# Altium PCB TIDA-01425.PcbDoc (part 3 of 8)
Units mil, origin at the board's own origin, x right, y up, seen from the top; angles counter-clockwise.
Board outline 7000 x 3600 mil, 6 copper layers (Layer 1 - Top Layer, Layer 2 - GND, Layer 3 - Signal / PWR, Layer 4 - Signal / PWR, Layer 5 - PWR, Layer 6 - Bottom Layer), stack 60.4 mil thick; 495 components, 307 nets, 2058 pads, 1870 vias.
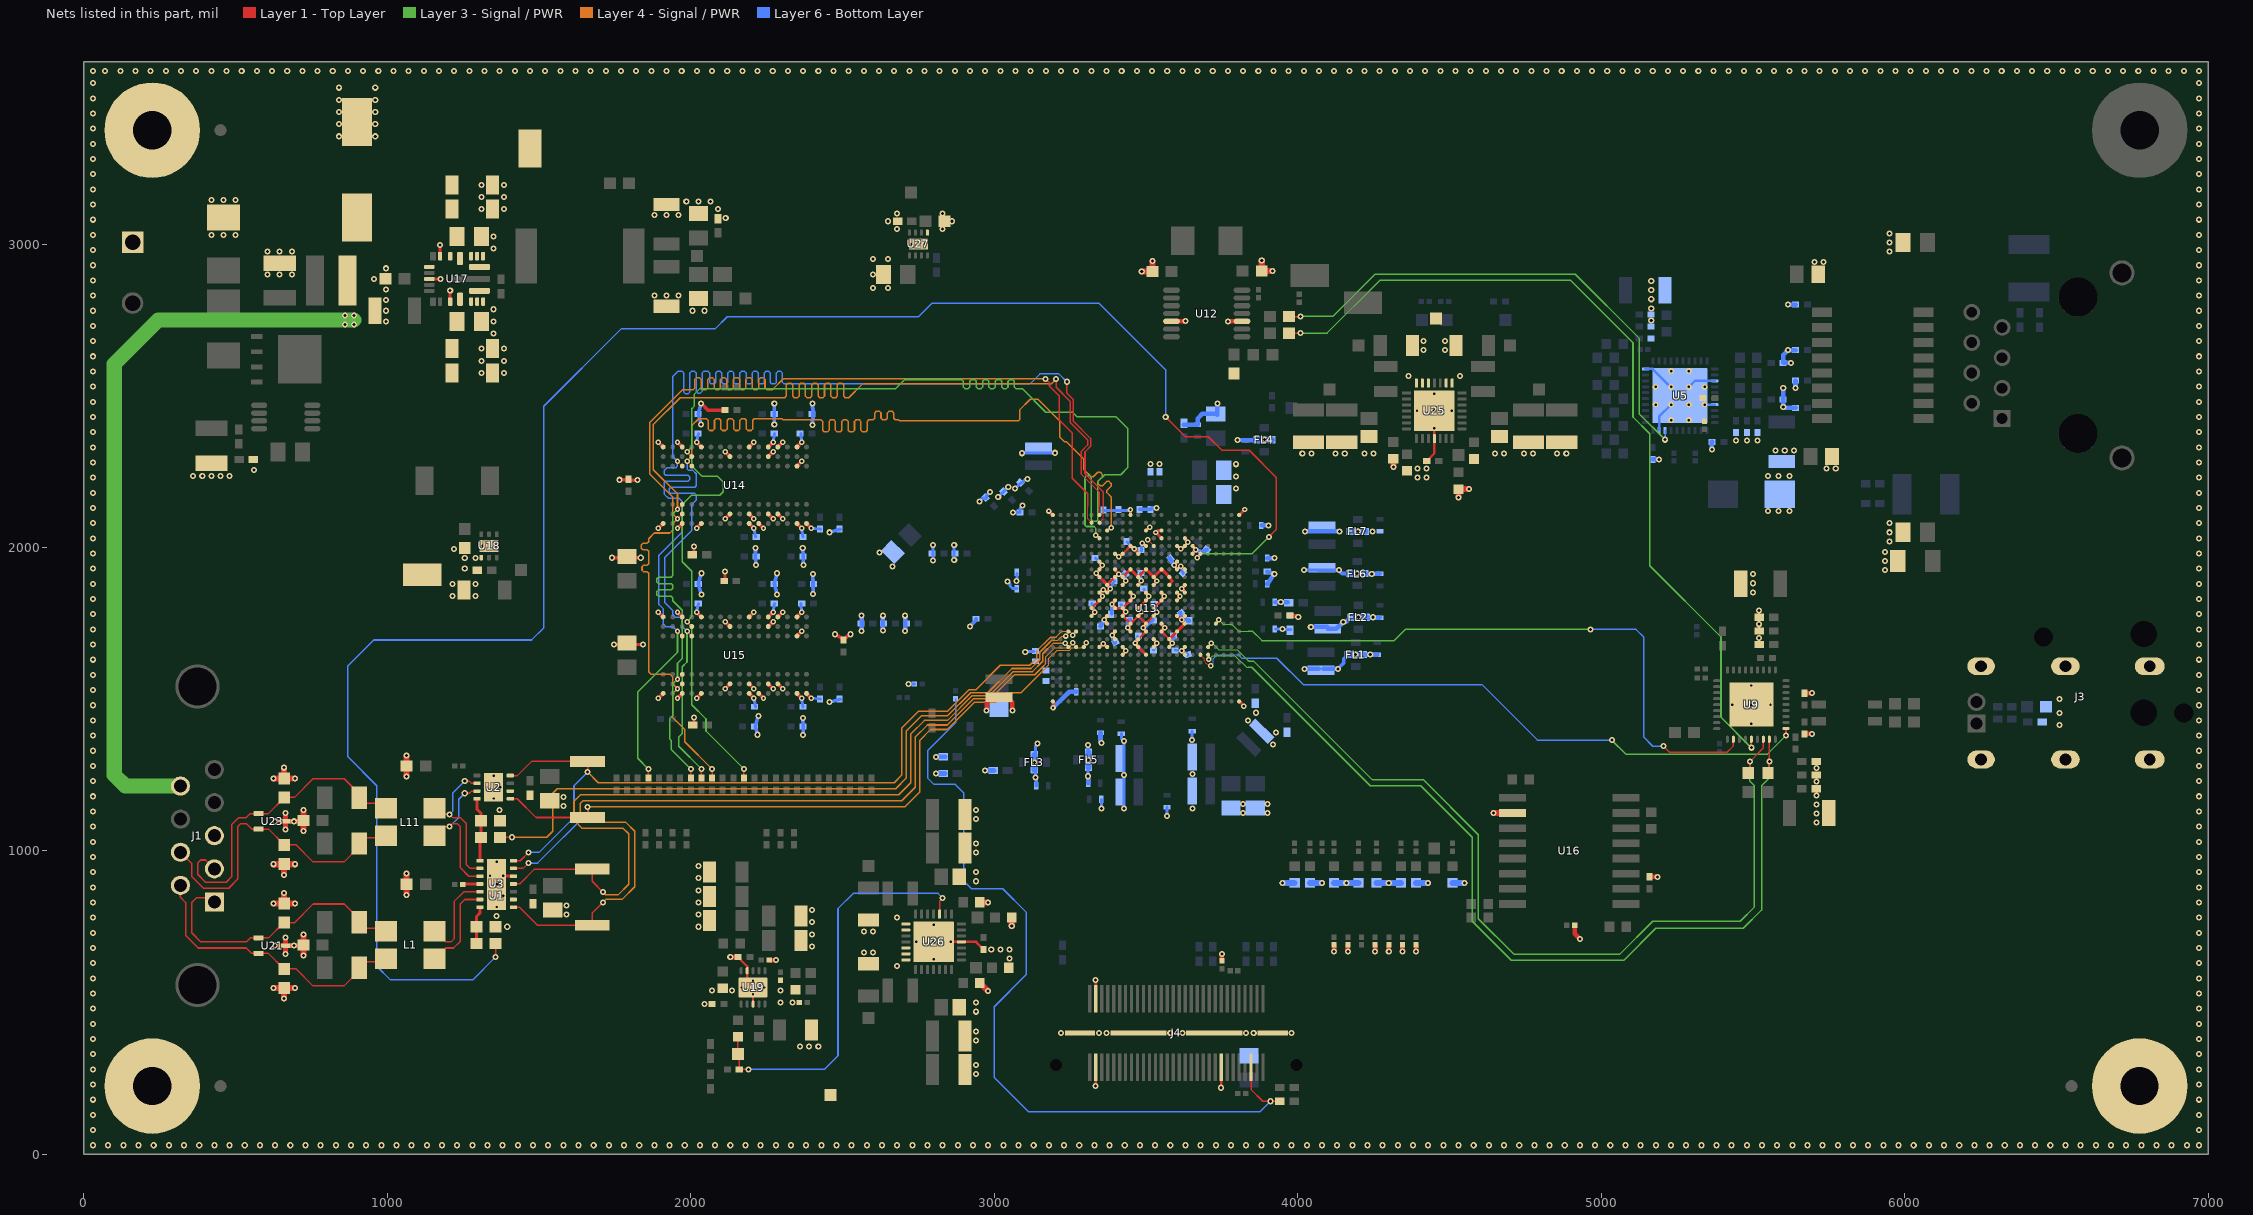
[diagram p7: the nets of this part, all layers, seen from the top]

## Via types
v1: diameter 20, hole 10, Layer 1 - Top Layer to Layer 6 - Bottom Layer, tented both sides, 1119 vias
v2: diameter 20, hole 9.99, Layer 1 - Top Layer to Layer 6 - Bottom Layer, tented both sides, 298 vias
v3: diameter 18, hole 7.99, Layer 1 - Top Layer to Layer 6 - Bottom Layer, tented both sides, 203 vias
v4: diameter 18, hole 8, Layer 1 - Top Layer to Layer 6 - Bottom Layer, tented both sides, 177 vias
v5: diameter 19.68, hole 7.87, Layer 1 - Top Layer to Layer 6 - Bottom Layer, tented both sides, 41 vias
v6: diameter 20, hole 10, Layer 1 - Top Layer to Layer 6 - Bottom Layer, 27 vias
v7: diameter 19.68, hole 7.87, Layer 1 - Top Layer to Layer 6 - Bottom Layer, 5 vias

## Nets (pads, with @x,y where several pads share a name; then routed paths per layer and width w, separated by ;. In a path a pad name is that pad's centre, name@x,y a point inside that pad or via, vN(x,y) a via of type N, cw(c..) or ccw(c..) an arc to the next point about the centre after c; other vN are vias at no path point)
BOARD_12V: C164.1 C169.1 C170.1 C171.1 C172.1 C175.1 C176.1 J1.9 L4.2 U17.4 U17.14 U17.15 U17.18 | length 2438.3
  Layer 3 - Signal / PWR w50: J1.9@318.11,1213.58 136.42,1213.58 100,1250 100,2605 245,2750 890,2750
  other v1: 860,2735 890,2735 860,2765 890,2765
CAN1_STB: R4.1 R6.2 U1.8 U3.14 | length 123.9
  Layer 1 - Top Layer w10: R4.1@1293.5,695 R6.2@1293.5,750 1293.5,783.5 1304.88,794.88 U3.14@1304.88,814.23
CAN2_STB: R8.1 R10.2 U2.8 U3.8 | length 211
  Layer 1 - Top Layer w10: U2.8@1294.88,1171.61 1294.88,1138.12 1308.51,1124.49 R10.2@1308.51,1098.9 1308.51,1038.9 1304.88,1035.28 U3.8@1304.88,967.77
CAN_VIO: R3.1 U1.5 U3.11 | length 55.9
  Layer 1 - Top Layer w10: R3.1@1248.98,890.98 U3.11@1304.88,891
CANH_1: L1.2 U1.7 U3.13 | length 303.2
  Layer 1 - Top Layer w5: L1.2@1154.72,644.72 1157.72,644.72 1193,680 1218.28,680 1240,701.72 1240,825 1254.8,839.8 U3.13@1304.88,839.82
CANH_1_OUT: C248.1 J1.6 L1.1 R7.1 U21.2 | length 944
  Layer 1 - Top Layer w5: J1.6@318.11,886.42 318.11,846.89 335,830 335,721.72 376.72,680 535,680 552.99,662.01 U21.2@575.71,662.01 607.99,662.01 658.5,611.5 C248.1@660,611.5 698.5,611.5 755,555 857,555 907.09,605.09 R7.1@907.09,615 927.09,635 985.55,635 L1.1@995.28,644.72
CANH_2: L11.2 U2.7 U3.10 | length 489.3
  Layer 1 - Top Layer w5: L11.2@1154.72,1054.72 1180,1080 v1(1205,1080) 1215,1090 1230,1090 1240,1080 1240,945 1268.41,916.59 U3.10@1304.88,916.59 ; v1(1255,1190) 1270,1190 1277.2,1197.2 U2.7@1294.88,1197.2
  Layer 6 - Bottom Layer w5: v1(1205,1080) 1235,1110 1235,1170 v1(1255,1190)
CANH_2_OUT: C163.1 J1.7 L11.1 R151.1 U23.2 | length 1037
  Layer 1 - Top Layer w5: J1.7@318.11,995.47 355,958.58 355,916 394,877 477,877 507,907 507,1080 517,1090 535,1090 552.99,1072.01 U23.2@575.71,1072.01 607.99,1072.01 C163.1@660,1020 ; C163.1@660,1019.09 C163.1@660,1020 ; L11.1@995.28,1053.23 985.55,1043.5 927.09,1043.5 907.09,1023.5 907.09,1013.59 857,963.5 755,963.5 698.5,1020 C163.1@660,1020
CANL_1: L1.3 U1.6 U3.12 | length 305.5
  Layer 1 - Top Layer w5: L1.3@1154.72,735.28 1157.72,735.28 1193,700 1210,700 1220,710 1220,833.28 1252.11,865.39 U3.12@1304.88,865.41
CANL_1_OUT: C1.1 J1.1 L1.4 R5.2 U21.1 | length 934.6
  Layer 1 - Top Layer w5: J1.1@429.92,831.89 416.81,845 370,845 355,830 355,730 385,700 535,700 548.19,713.19 U21.1@575.71,713.19 608.19,713.19 658.5,763.5 C1.1@660,763.5 693.5,763.5 755,825 858,825 907.09,775.91 R5.2@907.09,765 927.09,745 985.55,745 L1.4@995.28,735.28
CANL_2: L11.3 U2.6 U3.9 | length 486.9
  Layer 1 - Top Layer w5: L11.3@1154.72,1145.28 1180,1120 v1(1205,1120) 1215,1110 1240,1110 1260,1090 1260,955 1272.82,942.18 U3.9@1304.88,942.18 ; v1(1255,1230) 1270,1230 1277.2,1222.8 U2.6@1294.88,1222.8
  Layer 6 - Bottom Layer w5: v1(1205,1120) 1215,1130 1215,1190 v1(1255,1230)
CANL_2_OUT: C160.1 J1.2 L11.4 R150.2 U23.1 | length 1040.5
  Layer 1 - Top Layer w5: J1.2@440.87,930 J1.2@429.92,940.94 400.87,970 385,970 375,960 375,923 401,897 468.72,897 487,915.28 487,1087 510,1110 535,1110 548.19,1123.19 U23.1@575.71,1123.19 608.19,1123.19 660,1175 C160.1@660,1176.1 693.5,1176.1 755,1237.6 858,1237.6 907.09,1188.51 907.09,1177.6 927.09,1157.6 985.55,1157.6 L11.4@995.28,1147.87
DCAN1_RX: "CAN1 RX.1" U1.4 U3.4 U13.H23 | length 2859.9
  Layer 1 - Top Layer w4: v3(3233.7,1684.9) U13.H23@3244.09,1672.05
  Layer 1 - Top Layer w5: U3.4@1415.12,891 1436,891 1485,940 1675,940 1675,900 v2(1710,865)
  Layer 4 - Signal / PWR w5.25: v2(1710,865) 1720,855 1760,855 1795,890 1795,1056.72 1776.72,1075 1641.72,1075 1615,1101.72 1615,1163.28 1636.72,1185 2685,1185 2725,1225 2725,1385 2770,1430 2845.51,1430 2926.49,1510.99 2926.99,1510.99 2982.51,1511 3062.39,1590.88 3125.87,1590.88 3160,1625.01 3160,1625.5 3160.01,1650 3194.91,1684.9 v3(3233.7,1684.9)
DCAN1_STB: R4.2 U13.Y6 | length 6312.5
  Layer 1 - Top Layer w5: v1(1356.5,650) R4.2@1356.5,695 ; v1(3565,2430) 3630,2365 3705,2365 3750,2320 3840,2320 3930,2230 3930,2060 v1(3905,2035)
  Layer 1 - Top Layer w10: v3(3669.2,1966.7) U13.Y6@3679.13,1979.13
  Layer 3 - Signal / PWR w5.25: v3(3669.2,1966.7) 3681.64,1979.13 3849.13,1979.13 v1(3905,2035)
  Layer 6 - Bottom Layer w5: v1(1356.5,650) 1281.5,575 1010,575 965,620 965,1215 870,1310 870,1610 955,1695 1475,1695 1515,1735 1515,2465 1770,2720 2080,2720 2120,2760 2750,2760 2795,2805 3345,2805 3565,2585 v1(3565,2430)
DCAN1_TX: "CAN1 TX.1" U1.1 U3.1 U13.H22 | length 2900.1
  Layer 1 - Top Layer w4: v3(3258.1,1686) 3267.4,1674.34 U13.H22@3269.68,1672.05
  Layer 1 - Top Layer w5: U3.1@1415.12,814.23 1435.77,814.23 1495,755 1675,755 1675,795 v2(1710,830)
  Layer 4 - Signal / PWR w4: 3163,1610.51 3170,1617.51 3170,1620.51 3170.25,1620.76 3170.25,1621.25 3170.27,1640.26 3200.01,1670 3227.4,1670 3227.49,1669.91 3239.91,1669.91 3240,1670 3245,1670 3258.1,1683.1 v3(3258.1,1686)
  Layer 4 - Signal / PWR w5.25: v2(1710,830) 1720,840 1773.28,840 1815,881.72 1815,1065 1785,1095 1650,1095 1635,1110 1635,1155 1645,1165 2695,1165 2740,1210 2740,1375 2780,1415 2845.01,1415 2930.74,1500.74 2931.24,1500.74 2986.76,1500.75 3066.64,1580.63 3133.12,1580.63 3163,1610.51
DCAN2_RX: "CAN2 RX.1" U2.4 U3.7 U13.K22 | length 2683.3
  Layer 1 - Top Layer w4: v3(3259.3,1710.7) U13.K22@3269.68,1723.23
  Layer 1 - Top Layer w5: U2.4@1405.12,1248.39 1428.39,1248.39 1475,1295 1660,1295 ; U3.7@1415.12,967.77 1437.77,967.77 v1(1465,995)
  Layer 1 - Top Layer w5.25: v1(1660,1260) 1660,1295
  Layer 4 - Signal / PWR w4: 3204.56,1705.15 3222.55,1723.14 3246.86,1723.14 v3(3259.3,1710.7)
  Layer 4 - Signal / PWR w5.25: v1(1660,1260) 1695,1225 2670,1225 2695,1250 2695,1405 2750,1460 2845.5,1460 2916.99,1531.5 2939.98,1531.5 3019.86,1611.38 3116.88,1611.38 3139.5,1634 3139.5,1649.99 3139.49,1658.48 3184.91,1703.9 3203.31,1703.9 3204.56,1705.15
  Layer 6 - Bottom Layer w5: v1(1465,995) 1500,995 1615,1110 1615,1215 v1(1660,1260)
DCAN2_STB: R8.2 U13.K23 | length 2336.2
  Layer 1 - Top Layer w4: v3(3236.1,1708.1) 3244.09,1715.59 U13.K23@3244.09,1723.23
  Layer 1 - Top Layer w5: R8.2@1371.5,1045 v1(1410,1045)
  Layer 4 - Signal / PWR w4: 3186.17,1690.66 3190.17,1694.66 3209.66,1694.66 3223.1,1708.1 v3(3236.1,1708.1)
  Layer 4 - Signal / PWR w5.25: v1(1410,1045) 1525,1045 1545,1065 1545,1190 1560,1205 2675,1205 2710,1240 2710,1395 2760,1445 2846.01,1445 2922.24,1521.24 2922.74,1521.24 2978.26,1521.25 3058.14,1601.13 3121.13,1601.13 3149.76,1629.76 3149.76,1647.75 3149.75,1654.24 3186.17,1690.66
DCAN2_TX: "CAN2 TX.1" U2.1 U3.6 U13.H21 | length 2651.5
  Layer 1 - Top Layer w4: U13.H21@3295.28,1672.05 v3(3303.2,1685.7)
  Layer 1 - Top Layer w5: U3.6@1415.12,942.18 1447.18,942.18 v1(1465,960)
  Layer 1 - Top Layer w5.25: U2.1@1405.12,1171.61 1428.39,1171.61 1490,1110 1660,1110 v1(1660,1145)
  Layer 4 - Signal / PWR w4: 3163,1596.01 3180,1613.01 3180,1635 3207.01,1662.01 3224.09,1662.01 3224.18,1661.92 3243.22,1661.92 3243.31,1662.01 3248.31,1662.01 3255.65,1669.35 3286.85,1669.35 v3(3303.2,1685.7)
  Layer 4 - Signal / PWR w5.25: v1(1660,1145) 2705,1145 2755,1195 2755,1365 2790.13,1400.13 2845.13,1400.13 2905.37,1460.37 ; 2905.37,1460.4 2915.11,1470.14 ; 2915.14,1470.14 2935.5,1490.5 3005.58,1490.5 3035.71,1520.63 3087.62,1520.63 3163,1596.01
  Layer 6 - Bottom Layer w5: v1(1465,960) 1495,960 1660,1125 v1(1660,1145)
"DDR EN": R69.2 R145.1 TP63.1 U26.10 | length 1368
  Layer 1 - Top Layer w5: R69.2@2155,387.44 TP63.1@2155,330 2159.68,325.32 R145.1@2159.68,280 v1(2190,280) ; U26.10@2819.69,791.54 2819.69,834.69 v1(2830,845)
  Layer 6 - Bottom Layer w5: v1(2190,280) 2440,280 2485,325 2485,810 2535,860 2815,860 v1(2830,845)
EMU_RSTN: J4.6 R52.1 R114.1 | length 2722.9
  Layer 1 - Top Layer w5: J4.6@3846.07,287.21 3846.07,213.93 3885,175 v1(3910,175) R52.1@3941.38,175
  Layer 6 - Bottom Layer w5: R114.1@2873,1502.01 2873,1423 2780,1330 2780,1240 2800,1220 2870,1220 2900,1190 2900,900 2925,875 3028.28,875 3105,798.28 3105,591.57 3000,486.57 3000,253.43 3113.43,140 3875,140 v1(3910,175)
ENET_EN: R34.2 U9.7 U13.H5 | length 3075.3
  Layer 1 - Top Layer w4: U13.H5@3704.8,1672 3713.11,1683.64 3714.13,1683.81 v3(3714.7,1684.6)
  Layer 1 - Top Layer w5: R34.2@5485,1256.5 5490,1261.5 v2(5490,1295) 5534.37,1339.37 U9.7@5534.37,1367.83
  Layer 3 - Signal / PWR w4: v3(3714.7,1684.6) 3715.3,1684 3718,1684 3739.68,1662.32 3801.48,1662.32 3836.8,1627 3837,1627
  Layer 3 - Signal / PWR w5.25: 3837,1627 3838.37,1625.63 3854.37,1625.63 4245,1235 4413.43,1235 4595,1053.43 4595,776.72 4711.72,660 5061.72,660 5170.25,768.54 5458.54,768.54 5505,815 5505,1215 5490,1230 v2(5490,1295)
ENET_INH: U9.10 U13.G6 | length 2158.6
  Layer 1 - Top Layer w4: U13.G6@3679.13,1646.46 3691.69,1633.9 3691.69,1626.62 3695.02,1619.77 3701.2,1615.1 3711.36,1612.89 v3(3713.4,1609.7)
  Layer 1 - Top Layer w5.25: v1(5609.17,1380) U9.10@5609.17,1403.26
  Layer 3 - Signal / PWR w5.25: v1(5035,1365) 5081,1319 5548.17,1319 v1(5609.17,1380)
  Layer 6 - Bottom Layer w4: v3(3713.4,1609.7) 3721.84,1618.14 3721.84,1633.84 3734.1,1646.1 3804.9,1646.1 3816,1635
  Layer 6 - Bottom Layer w5: 3816,1635 3931,1635 4018,1548 4607,1548 4790,1365 v1(5035,1365)
ENET_INTSN: U9.2 U13.L4 | length 2147.2
  Layer 1 - Top Layer w4: U13.L4@3730.4,1748.8 v3(3740.3,1761.6)
  Layer 1 - Top Layer w5: v1(5205,1345) 5225,1325 5415,1325 5435.94,1345.94 U9.2@5435.94,1367.83
  Layer 3 - Signal / PWR w4: v3(3740.3,1761.6) 3755.39,1746.51 3783,1746.51 3806.26,1723.25 3837,1723.25
  Layer 3 - Signal / PWR w5.25: 3837,1723.25 3851.75,1723.25 3882,1693 4318,1693 4355,1730 v2(4965,1730)
  Layer 6 - Bottom Layer w5: v2(4965,1730) 5115,1730 5140,1705 5140,1375 5170,1345 v1(5205,1345)
ENET_WAKE: R35.2 U9.8 U13.G5 | length 3102.5
  Layer 1 - Top Layer w4: U13.G5@3704.72,1646.46 v3(3706.85,1630.85)
  Layer 1 - Top Layer w5: R35.2@5550,1256.5 5554.06,1260.55 v2(5554.06,1295) U9.8@5554.06,1367.83
  Layer 3 - Signal / PWR w4: v3(3706.85,1630.85) 3719.8,1643.8 3792.83,1643.8 3831.5,1605.13 3837,1605.13
  Layer 3 - Signal / PWR w5.25: 3837,1605.13 3848.87,1605.13 4239,1215 4405.15,1215 4575,1045.15 4575,768.43 4703.43,640 5075,640 5180,745 5468.28,745 5528.54,805.25 5528.54,1215 5554.06,1240.52 v2(5554.06,1295)
ETH_CLK0: R1.2 U5.28 | length 1699.5
  Layer 1 - Top Layer w5: R1.2@3971.5,2760.92 4008.81,2760.92 v1(4009.41,2761.52)
  Layer 3 - Signal / PWR w5.25: v1(4009.41,2761.52) 4116.52,2761.52 4255,2900 4915,2900 5125,2690 5125,2440.79 v1(5210.79,2355)
  Layer 6 - Bottom Layer w5: v1(5210.79,2355) U5.28@5210.79,2385.83
ETH_CLK1: R19.2 U9.5 | length 2814.9
  Layer 1 - Top Layer w5: R19.2@3971.5,2705.92 4008.81,2705.92 v1(4009.41,2706.52) ; v1(5495,1340) U9.5@5495,1367.83
  Layer 3 - Signal / PWR w5.25: v1(4009.41,2706.52) 4096.52,2706.52 4270,2880 4900,2880 5105,2675 5105,2430 5160,2375 5160,1940 5395,1705 5395,1440 v1(5495,1340)
GND: "GND 3V3Buck.1" "GND 5V0Boost.1" C1.2 C2.2 C3.2 C4.2 C5.2 C6.2 C7.2 C8.1 C9.2 C10.2 C11.1 C12.1 C13.2 C14.1 C15.2 C16.2 C17.2 C18.2 C19.2 C21.2 C22.2 C23.2 C24.2 C25.2 C27.2 C28.2 C29.2 C30.2 C31.2 C32.2 C33.2 C34.2 C35.2 C36.2 C37.2 C38.2 C39.2 C40.2 C41.2 C42.2 C43.2 C44.2 C45.2 C46.2 C47.2 C48.2 C49.2 C50.2 C51.2 C52.2 C53.2 C54.2 C55.2 C56.2 C57.2 C58.2 C59.2 C60.2 C62.2 C63.2 C64.2 C65.2 C66.2 C67.2 C68.2 C69.2 C70.2 C71.2 C72.2 C73.2 C74.2 C75.2 C76.2 C77.2 C79.2 C80.2 C81.2 C82.2 C83.2 C84.2 C85.2 C86.2 C87.2 C88.2 C89.2 C90.2 C91.2 C92.2 C93.2 C94.2 C95.2 C96.2 C97.2 C98.2 C99.2 C100.2 C101.2 C102.2 C103.2 C104.2 C105.2 C106.2 C107.2 C108.2 C109.2 C110.2 C111.2 C112.2 C113.2 C114.2 C115.2 C116.2 C117.2 C118.2 C119.2 C120.2 C122.2 C123.2 C124.2 C125.2 C126.2 C127.2 C128.2 C129.2 C130.2 C131.1 C132.1 C133.2 C134.2 C135.2 C136.2 C137.2 C138.2 C139.2 C140.2 C141.2 C142.2 C147.2 C149.2 C150.2 C151.2 C152.2 C153.2 C154.2 C155.2 C156.2 C157.2 C158.2 C159.2 C160.2 C161.2 C163.2 C164.2 C166.2 C167.1 C168.2 C169.2 C170.2 C171.2 C172.2 C173.2 C174.2 C175.2 C176.2 C177.2 C178.2 C179.2 C180.2 C183.2 C184.2 C185.2 C186.2 C187.2 C188.2 C189.2 C190.2 C191.2 C192.2 C193.2 C194.2 C195.2 C196.2 C197.2 C198.2 C199.2 C222.2 C228.2 C229.2 C230.2 C231.2 C232.2 C233.2 C234.2 C235.2 C236.2 C237.2 C238.2 C239.2 C240.2 C241.2 C242.2 C243.2 C244.2 C245.2 C246.2 C247.2 C248.2 C249.2 C250.2 C251.2 C252.2 C253.2 C255.2 C256.2 C257.2 C258.2 C259.2 C260.2 C261.2 C262.2 C263.2 C264.2 C265.2 C266.2 C267.2 C268.2 C269.2 C270.2 C271.2 D3.1 FL1.2 FL2.2 FL3.2 FL4.2 FL5.2 FL6.2 FL7.2 H1.1 H3.1 H4.1 J1.3 J3.S1 J3.S2 J3.S3 J3.S4 J3.S5 J3.S6 J4.16 J4.57 J4.58 J4.MP1 J4.MP2 J4.MP3 J4.MP4 J5.1 R6.1 R10.1 R21.2 R28.1 R36.1 R37.1 R43.2 R45.2 R47.2 R58.1 R59.1 R79.2 R95.2 R98.1 R103.1 R105.2 R106.2 R107.1 R110.2 R111.1 R117.1 R119.2 R121.1 R123.2 R125.1 R127.1 TP1.1 TP2.1 U1.2 U1.9@1360,852.6 U2.2 U2.9@1350,1210 U3.2 U3.5 U3.15 U4.2 U5.13 U5.17 U5.29 U5.40 U5.41@5260,2500 U6.2 U7.2 U8.2 U9.37 U10.2 U11.2 U12.5 U12.10 U13.A1 U13.A25 U13.AA7 U13.AA8 U13.AA9 U13.AA12 U13.AA13 U13.AA15 U13.AB8 U13.AB11 U13.AC11 U13.AC13 U13.AE1 U13.AE15 U13.AE25 U13.G8 U13.G13 U13.G16 U13.H8 U13.H10 U13.H12 U13.H14 U13.H16 U13.H18 U13.H19 U13.J10 U13.J12 U13.J14 U13.J17 U13.K9 U13.K11 U13.K13 U13.K15 U13.K17 U13.L8 U13.L11 U13.L13 U13.L15 U13.L18 U13.M8 U13.M9 U13.M12 U13.M14 U13.M16 U13.M18 U13.M20 U13.N12 U13.N14 U13.N16 U13.N17 U13.N20 U13.P9 U13.P11 U13.P13 U13.P15 U13.P17 U13.P19 U13.R8 U13.R9 U13.R11 U13.R13 U13.R15 U13.R18 U13.R19 U13.T8 U13.T10 U13.T12 U13.T14 U13.T16 U13.T18 U13.U10 U13.U12 U13.U14 U13.U16 U13.U17 U13.U19 U13.V8 U13.V9 U13.V11 U13.V13 U13.V15 U13.V17 U13.V19 U13.W9 U13.W19 U13.Y7 U13.Y14 U13.Y16 U13.Y17 U14.A9 U14.B1 U14.B3 U14.B9 U14.D1 U14.D8 U14.E1 U14.E2 U14.E8 U14.F9 U14.G1 U14.G8 U14.G9 U14.J2 U14.J8 U14.M1 U14.M9 U14.P1 U14.P9 U14.T1 U14.T9 U15.A9 U15.B1 U15.B3 U15.B9 U15.D1 U15.D8 U15.E1 U15.E2 U15.E8 U15.F9 U15.G1 U15.G8 U15.G9 U15.J2 U15.J8 U15.M1 U15.M9 U15.P1 U15.P9 U15.T1 U15.T9 U16.10 U17.3 U17.5 U17.6 U17.7 U17.8 U17.10 U17.11 U17.12 U17.13 U17.16 U17.20 U18.1 U18.7@1335,2005 U19.4 U19.8 U19.11 U21.3 U23.3 U25.4 U25.15 U25.16 U25.19 U25.20 U25.21 U25.29 U26.4 U26.15 U26.16 U26.19 U26.20 U26.21 U26.29 U27.5 U27.9 | length 12469.8
  Layer 1 - Top Layer w4: v3(3506.4,2024.8) 3525.59,2005.61 U13.AA12@3525.59,2004.72
  Layer 1 - Top Layer w8: C187.2@2155.32,650 2155.32,649.68 2185.32,619.68 U19.4@2185.32,605.12 U19.11@2185.32,569.68 ; U19.8@2205,494.88 v5(2205,527.36) ; v7(2857.09,700) U26.4@2891.54,700 2940,700 C266.2@2964.69,675.31 ; U13.N20@3320.87,1800 U13.P19@3346.46,1825.59 ; v1(3334.26,225.01) J4.58@3334.26,287.21 ; J4.57@3334.26,512.8 v1(3334.26,575) ; U13.N17@3397.64,1800 U13.N16@3423.23,1800 U13.P15@3448.82,1825.59 ; U13.M16@3423.23,1774.41 U13.L15@3448.82,1748.82 U13.M14@3474.41,1774.41 U13.L13@3500,1748.82 U13.M12@3525.59,1774.41 ; U13.Y16@3423.23,1979.13 U13.AA15@3448.82,2004.72 ; U13.J14@3474.41,1697.64 U13.K13@3500,1723.23 ; U13.N14@3474.41,1800 U13.P13@3500,1825.59 ; U13.N12@3525.59,1800 U13.P11@3551.18,1825.59 ; U13.K11@3551.18,1723.23 U13.J10@3576.77,1697.64 ; v1(3747.64,219.42) J4.16@3747.64,287.21 ; C247.2@4425.31,2285 4425.31,2285.31 4450,2310 U25.4@4450,2358.46 v5(4450,2392.91)
  Layer 1 - Top Layer w10: U17.20@1138.19,2885 v1(1175,2885) ; U17.16@1173.62,2959.8 v1(1173.62,2996.61) ; U17.3@1207.09,2810.2 v1(1207.09,2847.01) ; U3.15@1385.59,916.59 U3.5@1415.12,916.59 ; v1(1740,1966) v1(1835,1966) ; v1(1747.5,1680.5) v1(1842.5,1680.5) ; R37.1@2010,1410 v1(2010,1440) ; R36.1@2010,1970 v1(2010,2002.5) ; C79.2@2112.5,1890 v1@2112.5,1920.5 ; U15.G8@2192.24,1550.51 v4(2207.98,1534.77) ; U13.A25@3192.91,1492.91 3192.91,1477.09 3193.59,1476.41 v3(3193.59,1471.22) ; U13.M20@3320.83,1774.43 v3(3330.5,1787.1) U13.N20@3320.87,1800 ; U13.W19@3346.4,1953.6 U13.W19@3346.46,1953.54 3356,1944 v3(3356,1941) 3356,1937.6 3346.4,1928 v3(3336.4,1914.9) U13.U19@3346.46,1902.36 U13.T18@3372.05,1876.77 ; U13.H19@3346.46,1672.05 v3(3359.03,1682.37) 3358.89,1682.59 3359.09,1682.43 U13.H18@3372.05,1672.05 ; U13.P19@3346.46,1825.59 v3(3356.7,1838.8) U13.R19@3346.43,1851.16 ; U13.R19@3346.43,1851.22 v3(3359.2,1860.4) 3372.05,1851.18 v3(3381.5,1863.9) U13.T18@3372.05,1876.77 ; U13.Y17@3397.6,1979.2 3397.66,1979.16 v3(3410.3,1969.6) U13.Y16@3423.23,1979.13 ; U13.V17@3397.64,1927.95 v3(3410.7,1912.2) ; U13.T16@3423.23,1876.77 v3(3432.8,1889.6) U13.U16@3423.23,1902.36 ; U13.G16@3423.23,1646.46 v3(3433.1,1659.1) U13.H16@3423.23,1672.05 ; U13.AE15@3448.82,2107.09 v3(3448.82,2124.04) ; U13.H14@3474.41,1672.05 U13.G13@3500,1646.46 ; U13.T14@3474.41,1876.77 v3(3484.25,1889.65) U13.U14@3474.41,1902.36 ; U13.AC13@3500,2056 3511.8,2066 v3(3512.3,2066) ; U13.H12@3525.59,1672.05 v3(3534.8,1684.8) U13.J12@3525.59,1697.64 ; U13.M12@3525.59,1774.41 v3(3535.4,1787) U13.N12@3525.59,1800 ; U13.T12@3525.59,1876.77 v3(3535.5,1889.4) U13.U12@3525.59,1902.36 ; U13.AB11@3551.2,2030.4 3551,2030.4 v3(3532.1,2049.3) 3538.8,2056 U13.AC11@3551.2,2056 ; U13.H10@3576.77,1672.05 v3(3586.85,1684.65) U13.J10@3576.77,1697.64 U13.L8@3627.95,1748.82 v3(3617.7,1761.7) ; U13.U10@3576.77,1902.36 U13.V11@3551.18,1927.95 ; U13.T10@3576.77,1876.77 3587.1,1889.4 3580.2,1896.3 3580.2,1900.3 3552.55,1927.95 U13.V11@3551.18,1927.95 ; U13.M9@3602.36,1774.41 v3(3617.7,1761.7) ; U13.W9@3602.4,1953.6 U13.W9@3602.36,1953.54 v3(3592.5,1940.9) 3602.36,1927.95 v3(3615,1937.7) U13.V8@3627.95,1927.95 ; U13.G8@3627.95,1646.46 v3(3617.5,1659.3) U13.H8@3627.95,1672.05 ; U13.M8@3627.95,1774.41 v3(3617.7,1761.7) ; U13.A1@3807.09,1492.91 v3(3822.7,1477.3) ; U13.AE1@3807.09,2107.09 v3(3825,2125) ; U13.T18@3372.05,1876.77 U13.U17@3397.64,1902.36 v3(3410.7,1912.2) ; v3(3410.7,1912.2) U13.U16@3423.23,1902.36 ; U13.U16@3423.23,1902.36 3448.82,1927.95 U13.U14@3474.41,1902.36 ; U13.U14@3474.41,1902.36 3500,1927.95 U13.U12@3525.59,1902.36 ; U13.U12@3525.59,1902.36 U13.V11@3551.18,1927.95
  Layer 1 - Top Layer w12: v1(1765,2223) C72.2@1794.96,2222.5 ; C72.2@1795,2222.5 v1(1824,2222) ; v4(1893.03,1503.26) U15.T9@1908.78,1519.02 ; v4(1893.03,1786.73) U15.T1@1908.78,1770.98 ; v4(1893.03,2063.26) U14.T9@1908.78,2079.02 ; v4(1893.03,2346.73) U14.T1@1908.78,2330.98 ; v4(1956.03,1503.27) U15.P9@1971.77,1519.02 ; v4(1956.03,1786.72) U15.P1@1971.77,1770.98 ; v4(1956.03,2063.27) U14.P9@1971.77,2079.02 ; v4(1956.03,2346.72) U14.P1@1971.77,2330.98 ; v4(2019.02,1503.27) U15.M9@2034.76,1519.02 ; v4(2019.02,1786.72) U15.M1@2034.76,1770.98 ; v4(2019.02,2063.27) U14.M9@2034.76,2079.02 ; v4(2019.02,2346.72) U14.M1@2034.76,2330.98 ; v1(2033.94,2475) 2056.44,2452.5 C62.2@2111.44,2452.5 ; v4(2113.51,1534.77) U15.J8@2129.25,1550.51 ; v4(2113.51,1755.22) U15.J2@2129.25,1739.49 ; v4(2113.51,2094.77) U14.J8@2129.25,2110.51 ; v4(2113.51,2315.22) U14.J2@2129.25,2299.49 ; U15.G9@2192.24,1519.02 v4(2207.98,1503.27) ; U15.G1@2192.24,1770.98 v4(2207.98,1786.72) ; U14.G9@2192.24,2079.02 v4(2207.98,2063.27) ; U14.G8@2192.24,2110.51 v4(2207.98,2094.77) ; U14.G1@2192.24,2330.98 v4(2207.98,2346.72) ; U15.F9@2223.74,1519.02 v4(2239.49,1503.26) ; U14.F9@2223.74,2079.02 v4(2239.49,2063.26) ; U15.E8@2255.24,1550.51 v4(2270.98,1534.77) ; U15.E2@2255.24,1739.49 v4(2270.98,1755.22) ; U15.E1@2255.24,1770.98 v4(2270.98,1786.72) ; U14.E8@2255.24,2110.51 v4(2270.98,2094.77) ; U14.E2@2255.24,2299.49 v4(2270.98,2315.22) ; U14.E1@2255.24,2330.98 v4(2270.98,2346.72) ; U15.D8@2286.73,1550.51 v4(2302.47,1534.77) ; U15.D1@2286.73,1770.98 v4(2302.47,1786.72) ; U14.D8@2286.73,2110.51 v4(2302.47,2094.77) ; U14.D1@2286.73,2330.98 v4(2302.47,2346.72) ; U15.B9@2349.72,1519.02 v4(2365.46,1503.27) ; U15.B3@2349.72,1707.99 v4(2365.46,1723.73) ; U15.B1@2349.72,1770.98 v4(2365.46,1786.72) ; U14.B9@2349.72,2079.02 v4(2365.46,2063.27) ; U14.B3@2349.72,2267.99 v4(2365.46,2283.73) ; U14.B1@2349.72,2330.98 v4(2365.46,2346.72) ; U15.A9@2381.22,1519.02 v4(2396.97,1503.26) ; U14.A9@2381.22,2079.02 v4(2396.97,2063.26) ; v1(2475,1714) 2502.5,1697.5 v1(2526,1714) ; v3(3180,2120) U13.AE25@3192.91,2107.09 ; U13.L18@3372.05,1748.82 v3(3362.5,1761.5) U13.M18@3372.05,1774.41 ; U13.J17@3397.64,1697.64 v3(3388.4,1710.5) U13.K17@3397.64,1723.23 ; U13.N17@3397.64,1800 v3(3388,1813) U13.P17@3397.64,1825.59 ; U13.M16@3423.23,1774.41 v3(3433,1787.5) U13.N16@3423.23,1800 ; U13.K15@3448.82,1723.23 v3(3439.5,1736) U13.L15@3448.82,1748.82 ; U13.P15@3448.82,1825.59 v3(3458.1,1838.5) U13.R15@3448.82,1851.18 ; U13.AA15@3448.82,2004.72 v3(3461.5,1995) U13.Y14@3474.4,1979.2 ; U13.H14@3474.41,1672.05 v3(3465,1685) U13.J14@3474.41,1697.64 ; U13.M14@3474.41,1774.41 v3(3484,1787.5) U13.N14@3474.41,1800 ; v3(3487.1,2013.8) U13.AA13@3500,2004.72 ; U13.K13@3500,1723.23 v3(3490.5,1736) U13.L13@3500,1748.82 ; U13.P13@3500,1825.59 v3(3509.5,1838.5) U13.R13@3500,1851.18 ; U13.K11@3551.18,1723.23 v3(3561.5,1736) U13.L11@3551.18,1748.82 ; U13.P11@3551.18,1825.59 v3(3560.5,1838.5) U13.R11@3551.18,1851.18 ; U13.P9@3602.36,1825.59 v3(3612,1838.5) U13.R9@3602.36,1851.18 ; U13.AA9@3602.36,2004.72 v3(3615.2,1995.2) 3627.94,2004.75 U13.AA8@3628,2004.8 ; U13.R8@3627.95,1851.18 v3(3618,1864) U13.T8@3627.95,1876.77 ; U13.AB8@3628.02,2030.37 v3(3637.5,2017.5) ; U13.Y7@3653.54,1979.13 v3(3663.5,1992) U13.AA7@3653.54,2004.72 ; C156.2@3974.69,1775 3997.65,1775 v1(4001.74,1770.91)
  Layer 1 - Top Layer w15: v1(630,687.6) U21.3@664.29,687.6 ; v1(630,1097.6) U23.3@664.29,1097.6 ; v1(664.29,660) U21.3@664.29,687.6 ; v1(664.29,715.2) U21.3@664.29,687.6 ; v1(664.29,1070) U23.3@664.29,1097.6 ; v1(664.29,1125.2) U23.3@664.29,1097.6 ; C2.2@721.1,687.6 v1(692.7,687.6) U21.3@664.29,687.6 ; C161.2@721.1,1097.6 v1(692.7,1097.6) U23.3@664.29,1097.6 ; v1(2130,650) C187.2@2155.32,650 ; C196.2@2257.99,640 v1(2280,640) ; v2(2975,1463) 2975,1490.5 2990.98,1506.47 C110.2@3016,1506.47 3043.4,1506.47 3059.6,1490.27 v2(3059.6,1463) ; U12.5@3583.86,2745.33 v1@3629.41,2745.33 ; R59.1@3750,637.99 v1(3750,660) ; v1@3770.59,2745.33 U12.10@3816.14,2745.33 ; v1(4120.08,668) R121.1@4120.08,690.01 ; v1(4165.08,668) R103.1@4165.08,690.01 ; v1(4255.08,668) R125.1@4255.08,690.01 ; v1(4300.08,668) R111.1@4300.08,690.01 ; v1(4345.08,668) R107.1@4345.08,690.01 ; v1(4390.08,668) R117.1@4390.08,690.01 ; R127.1@4912.99,755 4912.99,727.01 v1(4930,710) ; C7.2@5160,914.68 v1(5185.31,914.68) ; U11.2@5670,1385.32 v1(5695,1385.32) ; U10.2@5670,1519.68 v1(5695,1519.68)
  Layer 1 - Top Layer w20: v1(625,548.5) C248.2@660,548.5 ; v1(625,826.5) C1.2@660,826.5 ; v1(625,956.1) C163.2@660,956.1 ; v1(625,1239.09) C160.2@660,1239.09 ; v1(660,513.5) C248.2@660,548.5 ; v1(660,861.5) C1.2@660,826.5 ; v1(660,921.1) C163.2@660,956.1 ; v1(660,1274.09) C160.2@660,1239.09 ; v1(695,548.5) C248.2@660,548.5 ; v1(695,826.5) C1.2@660,826.5 ; v1(695,956.1) C163.2@660,956.1 ; v1(695,1239.09) C160.2@660,1239.09 ; v1(723.5,655) C2.2@723.5,690 v1(723.5,725) ; v1(723.5,1065) C161.2@723.5,1100 v1(723.5,1135) ; v1(1063.5,855) C252.2@1063.5,890 v1(1063.5,925) ; v1(1063.5,1245) C253.2@1063.5,1280 v1(1063.5,1315) ; C264.2@2952.56,565 v2(2978.78,538.78) ; C265.2@2952.56,830 v2(2980,830) ; v2(3057.56,752.56) C268.2@3057.56,780 ; v1(3486,2909.42) C222.2@3521,2909.42 v1(3521,2944.42) ; v1(3881.5,2945.92) C194.2@3881.5,2910.92 v1(3916.5,2910.92) ; v2(4315,2265) C245.2@4315,2292.44 ; v2(4530,2165) C250.2@4530,2192.44 v2(4565,2192.44) ; C246.2@4580,2292.44 C246.2@4582.56,2292.44 ; v1(4645,1125) U16.10@4707.99,1125
  Layer 6 - Bottom Layer w8: U5.40@5145.83,2588.58 5169.42,2588.58 5228.87,2529.13 v5(5230.87,2529.13) ; U5.29@5191.1,2385.83 5191.1,2431.1 v5(5230.87,2470.87) ; v5(5289.13,2529.13) 5309.21,2549.21 U5.13@5374.17,2549.21 ; v5(5340.71,2470.87) 5341.1,2470.47 U5.17@5374.17,2470.47
  Layer 6 - Bottom Layer w10: v4(2019.02,1786.72) 2024.99,1814.94 C83.2@2025,1815 ; v4(2019.02,2346.72) 2024.96,2374.78 C67.2@2025,2375 ; v4(2207.98,1503.27) 2212.43,1475.44 C80.2@2212.5,1475 ; v4(2207.98,2063.27) C65.2@2212.5,2035 ; v4(2270.98,1786.72) C82.2@2275,1814.96 ; v4(2270.98,2346.72) C68.2@2275,2374.96 ; C81.2@2362.5,1815 2362.53,1814.71 v4(2365.46,1786.72) ; C69.2@2362.5,2375 v4(2365.46,2346.72) ; v4(2365.46,1503.27) 2369.99,1475.05 C85.2@2370,1475 ; v4(2365.46,2063.27) 2369.99,2035.05 C63.2@2370,2035 ; v4(2396.97,1503.26) C84.2@2425,1500.31 C84.2@2427.5,1500 ; v4(2396.97,2063.26) C66.2@2425,2060.31 C66.2@2427.5,2060 ; v1(2718,1550) C231.2@2737.01,1550 ; v2(2798,1957) v2(2798,2008) ; v2(2868,1958) v2(2868,2008) ; v2(2952,2152) 2962.14,2162.14 2974.86,2162.14 2974.86,2171.86 v2(2986,2183) ; v2(3013,2166) 3029.86,2182.86 3029.86,2183.14 3030.14,2183.14 v2(3046,2199) ; v1(3043.87,1887.84) 3051.8,1879.91 3051.8,1873 3060.2,1864.6 C33.2@3074.6,1864.6 ; v2(3061.68,2115) 3084.68,2115 3084.68,2129 v2(3093.68,2138) ; v2(3069,2194) 3088.14,2213.14 3091.14,2213.14 3103,2225 v2(3110,2225) ; v2(3073.8,1890) 3074.8,1891 C45.2@3074.8,1914 ; v2(3092,2310.5) v2@3200,2310.5 ; v1(3102.04,1655.01) v1@3102.61,1655.01 ; v1@3104,1656.4 v1@3102.61,1655.01 ; C130.2@3130.5,1656.7 3106.89,1656.7 3105.2,1655.01 v1@3102.61,1655.01 ; v2(3136.4,1242.4) 3135.7,1243.1 3135.7,1345 3142,1351.3 v1(3142,1353.5) ; v2(3309.2,1246) v2(3309.2,1348.7) ; C129.2@3321.5,1815 3321.61,1814.65 v3(3330.5,1787.1) ; C138.2@3333,1965 3356,1942 v3(3356,1941) ; v1(3353,1140) C43.2@3353,1170 ; C126.2@3358,2121 3445.78,2121 v3(3448.82,2124.04) ; v3(3381.5,1863.9) 3395.68,1888.43 C139.2@3396,1889 ; C36.2@3387.1,1780.3 3387.1,1812.1 v3(3388,1813) ; v3(3410.7,1912.2) 3430.86,1912.2 3432.51,1913.86 C140.2@3432.92,1913.89 ; C102.2@3417.5,1812.5 3418.51,1810.88 v3(3433,1787.5) ; C38.2@3418.6,1386.2 3418.6,1371.4 v1(3427.9,1362.1) 3428,1362 v2(3428,1250) v2(3428,1140) ; C140.2@3431.92,1912.08 3432.8,1911.2 v3(3432.8,1889.6) ; C51.2@3438,2018 v3(3461.5,1995) ; v3(3465,1685) C115.2@3472,1707.2 ; C95.2@3482,1915 v3(3484.25,1889.65) ; C42.2@3485.5,1989 3485.57,1989.98 3485.69,1991.85 v3(3487.1,2013.8) ; v3(3490.5,1736) 3498,1736 C96.2@3524,1762 ; C97.2@3493,1863.5 v3(3509.5,1838.5) ; C105.2@3525.2,1661.6 v3(3534.8,1684.8) ; C34.2@3527.5,1813 v3(3535.4,1787) ; v1(3569,1115.7) C53.2@3569,1144 ; v3(3586.85,1684.65) C103.2@3592.4,1706.6 ; C106.2@3596,1662.8 3596.14,1662.77 v3(3617.5,1659.3) ; v3(3615,1937.7) 3621.7,1916.03 3621.81,1915.68 3622,1915.05 3622.09,1914.77 C128.2@3622.14,1914.59 ; v2@3651.5,1364.5 v2(3652,1365) C40.2@3652,1395 ; C44.2@3926.5,1731.5 v2(3950.2,1731.5) 3951.5,1730.2 C15.2@3978.2,1730.2 ; v2(4021,1925) C10.2@4068.1,1925
  Layer 6 - Bottom Layer w12: v1(2033.94,2405) C76.2@2023.94,2440 v1(2033.94,2475) ; v1(2035,1845) 2025,1880 v1(2035,1915) ; v1(2213,1998) 2212.5,1970.05 2212.5,1970 2212.53,1969.74 v1(2215,1942) ; v1(2220.27,1382.79) 2212.5,1410 v1(2222.5,1445) ; v1(2275,2405) v1(2275,2475) ; v1(2284.69,1845) C89.2@2274.69,1880 v1(2284.69,1915) ; v1(2368.86,1998.04) 2370,1970.01 v1(2371,1942) ; v1(2369,1438) 2370,1410.01 v1(2370,1382) ; v1(2401,2403) 2402.5,2439.89 2402.5,2440 2402.5,2440.12 v1(2401,2475) ; v1(2401.92,1912.95) C87.2@2402.5,1880 ; C87.2@2402.5,1879.97 v1(2403,1847) ; v1(2457.5,1490) 2490.27,1499.36 C88.2@2492.5,1500 ; v1(2457.5,2050) 2490.27,2059.36 C71.2@2492.5,2060 ; v1(2920,1740) 2940,1760 C149.2@2940,1765 ; v2(3136.4,1242.4) 3138,1240.8 C41.2@3138,1215 ; v3(3448.82,2124.04) v3@3449.78,2125 ; C153.2@3479,2125.31 C155.2@3515,2125.31 3519.69,2130 v1(3535,2130) ; v2(3801.61,2354) C46.2@3827,2354 ; FL4.2@3905,2355 FL4.2@3914.61,2355 ; C157.2@3975,1775 3997.65,1775 v1(4001.74,1770.91) ; C10.2@4068.1,1925 4133.8,1925 4134.5,1925.7 4146.2,1914 FL6.2@4171.39,1914 ; v2(4132.2,1600) 4152.2,1620 4152.2,1632.8 FL1.2@4166.39,1647 ; 4207.7,1914 4208.7,1913 v2(4244,1913)
  Layer 6 - Bottom Layer w15: v2(2563,1724) v2(2563,1776) ; v2(2633,1726) v2(2633,1775) ; v2(2706,1725) v2(2706,1775) ; v1(2808.62,1255) C122.2@2831.38,1255 C122.2@2838.62,1255 ; v1(2808.62,1310) C116.2@2831.38,1310 C116.2@2838.62,1310 ; v2(2970,1265) C32.2@3000,1265 ; v3(3193.59,1471.22) 3247.37,1525 C52.2@3270,1525 ; C50.2@3309,1223 3309,1245.79 v2(3309.2,1246) ; C37.2@3350,1390 3350,1359.4 v1(3353.2,1356.2) ; C152.2@3350,1740 v3(3362.5,1761.5) ; v3(3388.4,1710.5) 3396.68,1687.28 3396.94,1686.53 C47.2@3397.1,1686.08 ; v3(3439.5,1736) 3439.5,1753.5 C94.2@3448,1762 ; C239.2@3576.98,1966.26 3579.02,1962.92 v3(3592.5,1940.9) ; C125.2@3612.74,1785.52 3612.98,1784.36 3613.05,1784.02 v3(3617.7,1761.7) 3639.99,1759.34 3641.97,1759.13 3643.04,1759.02 C114.2@3643.22,1759 ; v3(3617.5,1659.3) C104.2@3635.43,1646.67 ; C49.2@3625,2405 C58.2@3670,2405 3670,2425 3685,2440 3733,2440 3735,2438 3735,2445 v2(3735,2475) ; v3(3663.5,1992) 3684.6,1984.8 C59.2@3699.52,1992.81 ; C46.2@3827,2354 3864.39,2354 FL4.2@3865.39,2355 ; C64.2@3881,2072.8 v1(3904.3,2072.8) ; C39.2@3899.7,1878.91 3900.3,1879.8 v2(3922.7,1913.21) C154.2@3900,1920 ; C54.2@3900,1965 v1(3923,1965) ; C55.2@3926,1819.7 v2(3944.1,1819.7) C48.2@3967,1820 ; v2(4021.8,1600) C27.2@4069,1600 ; v1@4024,2053.1 4087.8,2053.1 v2(4137,2053) v2@4140,2053 ; v1(4043,1738) C9.2@4098,1738 ; C27.2@4085,1600 v2(4132.2,1600) ; C9.2@4099,1731.47 4127.47,1731.47 4150,1754 v1(4150,1755) 4160.39,1755 FL2.2@4175.39,1770 ; FL1.2@4215.61,1646 C31.2@4262,1646 ; FL2.2@4224.61,1769 C35.2@4271,1769 ; v2(4244,1913) C56.2@4271,1913 ; C11.1@5170,2290.32 v1(5190,2290.32) ; v1(5365,2323) 5365,2347.68 C12.1@5365.31,2348 ; C4.2@5599.69,2488 5599.69,2463.31 v1(5600,2463) 5603,2460 U7.2@5640.31,2460 ; C4.2@5600,2488 v1(5600,2525) ; v1(5615.32,2800) U4.2@5640.32,2800 ; v1(5625,2608) C3.2@5599.69,2608 5599.69,2634.37 v1(5615.32,2650) U6.2@5640.32,2650 ; v1(5640.32,2525) U8.2@5640.32,2550
  Layer 6 - Bottom Layer w20: FL3.2@3132,1267.39 FL3.2@3132,1316.61 ; FL5.2@3311,1275.39 FL5.2@3311,1324.61 ; FL4.2@3865.39,2355 FL4.2@3914.61,2355 ; v1(3950,894.45) R123.2@3990,894.45 ; R119.2@4040,894.45 v1(4080,894.45) ; R105.2@4120,894.45 v1(4160,894.45) R110.2@4200,894.45 ; FL1.2@4166.39,1647 FL1.2@4215.61,1647 ; FL6.2@4171.39,1914 4207.7,1914 FL6.2@4220.61,1914 ; FL7.2@4173.39,2053 v1(4198,2053) FL7.2@4222.61,2053 ; FL2.2@4175.39,1770 FL2.2@4224.61,1770 ; R106.2@4260,894.45 v1(4300,894.45) R45.2@4340,894.45 ; R47.2@4390,894.45 v1(4430,894.45) ; R43.2@4510,894.45 v1(4550,894.45)
  other v1: 30,30 80,30 130,30 180,30 230,30 280,30 330,30 380,30 430,30 480,30 530,30 580,30 630,30 680,30 730,30 780,30 830,30 880,30 930,30 980,30 1030,30 1080,30 1130,30 1180,30 1230,30 1280,30 1330,30 1380,30 1430,30 1480,30 1530,30 1580,30 1630,30 1680,30 1730,30 1780,30 1830,30 1880,30 1930,30 1980,30 2030,30 2080,30 2130,30 2180,30 2230,30 2280,30 2330,30 2380,30 2430,30 2480,30 2530,30 2580,30 2630,30 2680,30 2730,30 2780,30 2830,30 2880,30 2930,30 2980,30 3030,30 3080,30 3130,30 3180,30 3230,30 3280,30 3330,30 3380,30 3430,30 3480,30 3530,30 3580,30 3630,30 3680,30 3730,30 3780,30 3830,30 3880,30 3930,30 3980,30 4030,30 4080,30 4130,30 4180,30 4230,30 4280,30 4330,30 4380,30 4430,30 4480,30 4530,30 4580,30 4630,30 4680,30 4730,30 4780,30 4830,30 4880,30 4930,30 4980,30 5030,30 5080,30 5130,30 5180,30 5230,30 5280,30 5330,30 5380,30 5430,30 5480,30 5530,30 5580,30 5630,30 5680,30 5730,30 5780,30 5830,30 5880,30 5930,30 5980,30 6030,30 6080,30 6130,30 6180,30 6230,30 6280,30 6330,30 6380,30 6430,30 6480,30 6530,30 6580,30 6630,30 6680,30 6730,30 6780,30 6830,30 6880,30 6930,30 6970,30 30,80 6970,80 30,130 6970,130 30,180 6970,180 30,230 6970,230 30,280 6970,280 30,330 6970,330 2360,355 2390,355 2420,355 30,380 6970,380 3220,400 3345,400 3370,400 3580,400 3620,400 3830,400 3855,400 3980,400 30,430 6970,430 30,480 6970,480 2045,495 2295,500 2335,500 30,530 6970,530 2070,540 2135,540 2295,540 30,580 6970,580 30,630 6970,630 30,680 6970,680 2400,685 2400,725 30,730 6970,730 1395,750 2025,750 2400,765 30,780 6970,780 1360,785 1590,790 2025,790 2400,805 1590,820 30,830 2025,830 6970,830 2025,870 30,880 6970,880 2025,910 30,930 6970,930 2025,950 30,980 6970,980 30,1030 6970,1030 30,1080 6970,1080 5710,1093 5710,1123 30,1130 6970,1130 1370,1135 1580,1147.4 5710,1153 1580,1177.4 30,1180 6970,1180 5710,1183 5710,1228 30,1230 6970,1230 5710,1273 30,1280 6970,1280 3132,1292 3311,1300 30,1330 6970,1330 30,1380 6970,1380 6510,1415 30,1430 6970,1430 6510,1455 30,1480 6970,1480 6510,1500 30,1530 6970,1530 30,1580 6970,1580 30,1630 6970,1630 4191,1647 4239,1647 30,1680 6970,1680 5520,1702 30,1730 6970,1730 5520,1747 4200,1770 4248,1770 30,1780 6970,1780 5520,1792 30,1830 6970,1830 1215,1840 1290,1840 5500,1852 30,1880 1215,1880 1290,1880 6970,1880 5500,1882 5500,1912 4196,1914 2112,1921 5935,1925 30,1930 1255,1930 6970,1930 5935,1955 1255,1965 1290,1965 30,1980 6970,1980 5935,1985 1220,1995 5950,2020 30,2030 6970,2030 5950,2050 4024,2053 4247,2053 30,2080 5950,2080 6970,2080 5550,2120 5585,2120 5620,2120 30,2130 6970,2130 30,2180 6970,2180 30,2230 6970,2230 360,2235 390,2235 420,2235 450,2235 480,2235 5550,2235 5585,2235 5620,2235 560,2255 5743.07,2260 5773.07,2260 30,2280 6970,2280 5575,2320 5605,2320 5635,2320 30,2330 6970,2330 5445,2353 5480,2353 5515,2353 3890,2355 30,2380 6970,2380 30,2430 6970,2430 30,2480 6970,2480 30,2530 6970,2530 1310,2575 1385,2575 30,2580 6970,2580 1310,2614.37 1385,2615 30,2630 6970,2630 1310,2655 1385,2655 30,2680 6970,2680 1350,2705 30,2730 6970,2730 995,2745 1350,2745 3770,2744.74 3630,2745.92 5165,2748 30,2780 995,2780 2005,2780 2045,2780 6970,2780 1350,2785 5165,2788 995,2815 5165,2818 30,2830 1880,2830 1920,2830 1960,2830 6970,2830 5165,2848 995.28,2850 2600,2855 2650,2855 5165,2878 30,2880 6970,2880 955.28,2885 605,2900 645,2900 685,2900 2600,2900 995.28,2920 30,2930 6970,2930 5702.34,2940 5732.34,2940 2600,2950 2650,2950 605,2975 645,2975 685,2975 5950,2975 30,2980 6970,2980 1350,2985 5950,3005 1350,3025 30,3030 420,3030 460,3030 500,3030 6970,3030 5950,3035 2680,3050 2830,3050 2650,3075 2860,3075 30,3080 6970,3080 2115,3085 1880,3095 1920,3095 1960,3095 2680,3100 2830,3100 1310,3115 1385,3115 2090,3115 30,3130 6970,3130 1985,3140 2025,3140 2065,3140 420,3145 460,3145 500,3145 1310,3155 1385,3155 30,3180 6970,3180 1310,3195 1385,3195 30,3230 6970,3230 30,3280 6970,3280 30,3330 6970,3330 840,3355 960,3355 30,3380 6970,3380 840,3395 960,3395 30,3430 6970,3430 840,3435 960,3435 840,3475 960,3475 30,3480 6970,3480 840,3515 960,3515 30,3530 6970,3530 30,3570 70,3570 120,3570 170,3570 220,3570 270,3570 320,3570 370,3570 420,3570 470,3570 520,3570 570,3570 620,3570 670,3570 720,3570 770,3570 820,3570 870,3570 920,3570 970,3570 1020,3570 1070,3570 1120,3570 1170,3570 1220,3570 1270,3570 1320,3570 1370,3570 1420,3570 1470,3570 1520,3570 1570,3570 1620,3570 1670,3570 1720,3570 1770,3570 1820,3570 1870,3570 1920,3570 1970,3570 2020,3570 2070,3570 2120,3570 2170,3570 2220,3570 2270,3570 2320,3570 2370,3570 2420,3570 2470,3570 2520,3570 2570,3570 2620,3570 2670,3570 2720,3570 2770,3570 2820,3570 2870,3570 2920,3570 2970,3570 3020,3570 3070,3570 3120,3570 3170,3570 3220,3570 3270,3570 3320,3570 3370,3570 3420,3570 3470,3570 3520,3570 3570,3570 3620,3570 3670,3570 3720,3570 3770,3570 3820,3570 3870,3570 3920,3570 3970,3570 4020,3570 4070,3570 4120,3570 4170,3570 4220,3570 4270,3570 4320,3570 4370,3570 4420,3570 4470,3570 4520,3570 4570,3570 4620,3570 4670,3570 4720,3570 4770,3570 4820,3570 4870,3570 4920,3570 4970,3570 5020,3570 5070,3570 5120,3570 5170,3570 5220,3570 5270,3570 5320,3570 5370,3570 5420,3570 5470,3570 5520,3570 5570,3570 5620,3570 5670,3570 5720,3570 5770,3570 5820,3570 5870,3570 5920,3570 5970,3570 6020,3570 6070,3570 6120,3570 6170,3570 6220,3570 6270,3570 6320,3570 6370,3570 6420,3570 6470,3570 6520,3570 6570,3570 6620,3570 6670,3570 6720,3570 6770,3570 6820,3570 6870,3570 6920,3570 6970,3570
  other v2: 2940,265 2940,295 2940,375 2940,405 2940,470 2940,500 2680,620 3050,645 2570,665 2600,665 2990,675 3020,675 3050,675 2570,735 2600,735 2680,780 2940,900 2940,930 2940,995 2940,1025 2940,1105 3820,1125 3900,1125 2940,1135 3653,1140 3820,1155 3900,1155 3653,1253 3918,1350 3929,1390 3836.2,1430.2 3861.9,1455.3 4136,1925 2665,1937 2622,1984 3796,2194.27 4395,2230 4425,2230 3796,2234.27 4395,2260 4425,2260 3796,2274.27 3515,2275 3545,2275 4015,2310 4045,2310 4125,2310 4155,2310 4220,2310 4250,2310 4650,2310 4680,2310 4745,2310 4775,2310 4855,2310 4885,2310 3200,2312 4365,2565 4535,2565 4415,2650 4485,2650 4415,2680 4485,2680
  other v5: 2167.6,550 2242.4,550 2205,572.64 1360,815.2 1338.35,852.6 1381.65,852.6 1360,890 1338.35,918.17 1381.65,918.17 1360,963.83 1350,1172.6 1328.35,1210 1371.65,1210 1350,1247.4 5495,1419.01 5432.01,1482 5495,1482 5557.99,1482 5495,1544.99 1313.35,2005 1356.65,2005 5230.87,2419.29 5289.13,2419.29 4392.91,2450 4450,2450 4507.09,2450 5179.29,2470.87 5289.13,2470.87 4450,2507.09 5179.29,2529.13 5340.71,2529.13 5230.87,2580.71 5289.13,2580.71 2728.35,3000 2771.65,3000
  other v7: 2800,642.91 2742.91,700 2800,700 2800,757.09
H_DDR1_A0: R67.1 U13.AC18 U14.N3 U15.N3 | length 3986.7
  Layer 1 - Top Layer w4: v4(1987.53,1723.73) U15.N3@2003.27,1707.99 ; v4(1987.53,2283.73) U14.N3@2003.27,2267.99 ; U13.AC18@3372.05,2055.91 v3(3384.9,2065.2)
  Layer 1 - Top Layer w5: R67.1@2035,1239.68 v1(2035,1270)
  Layer 3 - Signal / PWR w5.25: v4(1987.53,1723.73) 1987.53,1622.53 1971.7,1606.7 1971.7,1386.7 1960,1375 1960,1344.99 v1(2035,1270)
  Layer 4 - Signal / PWR w5.25: v4(1987.53,2283.73) 2003.3,2299.5 2003.3,2401.7 2025.75,2424.15 2051.63,2424.15 2056.88,2418.9 2056.88,2390.65 2062.13,2385.4 2072.63,2385.4 2077.88,2390.65 2077.88,2418.9 2083.13,2424.15 2093.63,2424.15 2098.88,2418.9 2098.88,2390.65 2104.13,2385.4 2114.63,2385.4 2119.88,2390.65 2119.88,2418.9 2125.13,2424.15 2135.63,2424.15 2140.88,2418.9 2140.88,2390.65 2146.13,2385.4 2156.63,2385.4 2161.88,2390.65 2161.88,2418.9 2167.13,2424.15 2177.63,2424.15 2182.88,2418.9 2182.88,2390.65 2188.13,2385.4 2198.63,2385.4 2203.88,2390.65 2203.88,2418.9 2209.13,2424.15 2300.06,2424.15 2303.58,2420.63 2429.25,2420.63 2434.5,2415.38 2434.5,2386.05 2439.75,2380.8 2450.25,2380.8 2455.5,2386.05 2455.5,2415.38 2460.75,2420.63 2471.25,2420.63 2476.5,2415.38 2476.5,2386.05 2481.75,2380.8 2492.25,2380.8 2497.5,2386.05 2497.5,2415.38 2502.75,2420.63 2513.25,2420.63 2518.5,2415.38 2518.5,2386.05 2523.75,2380.8 2534.25,2380.8 2539.5,2386.05 2539.5,2415.38 2544.75,2420.63 2555.25,2420.63 2560.5,2415.38 2560.5,2386.05 2565.75,2380.8 2576.25,2380.8 2581.5,2386.05 2581.5,2415.38 2586.75,2420.63 2600.52,2420.63 2605.77,2425.88 2605.77,2443.4 2611.02,2448.65 2621.52,2448.65 2626.77,2443.4 2626.77,2425.88 2632.02,2420.63 2642.52,2420.63 2647.77,2425.88 2647.77,2443.4 2653.02,2448.65 2663.52,2448.65 2668.77,2443.4 2668.77,2425.88 2674.02,2420.63 2684.27,2420.63 2687.7,2417.2 3078.7,2417.2 3083.3,2421.8 3083.3,2452.7 3118.7,2488.1 3144.4,2488.1 3215.8,2416.7 3215.8,2364 3231.6,2348.2 3238.2,2348.2 3294.9,2291.5 3294.9,2257.1 3319.19,2232.81 3326.61,2232.81 3341.44,2247.64 3348.86,2247.64 3356.29,2240.21 3356.29,2232.79 3341.46,2217.96 3341.46,2210.54 3348.89,2203.11 3356.31,2203.11 3370.9,2217.7 3378.32,2217.7 3385.75,2210.27 3385.75,2202.85 3371.16,2188.26 3371.16,2180.84 3384.9,2167.1 v3(3384.9,2065.2)
  Layer 6 - Bottom Layer w5: v4(1987.53,1723.73) 1971.53,1739.73 1971.53,1761.65 1962.46,1770.72 1948.28,1770.72 1940.53,1778.47 1940.53,1792.66 1915.19,1818 1914,1818 1914,1967 2003.52,2056.52 2003.52,2141.53 2018,2156.01 2018,2173.15 2013,2178.15 1934,2178.15 1929,2183.15 1929,2193.15 1934,2198.15 2013,2198.15 2018,2203.15 2018,2243 2007,2254 1992.53,2254 1987.53,2259 v4(1987.53,2283.73)
H_DDR1_A1: R68.1 U13.AE19 U14.P7 U15.P7 | length 3824.4
  Layer 1 - Top Layer w4: v4(1956.03,1566.26) U15.P7@1971.77,1582.01 ; U13.AE19@3346.46,2107.09 3346.46,2136
  Layer 1 - Top Layer w5: v4(1956.03,2126.26) U14.P7@1971.77,2142.01 ; R68.1@2000,1239.68 v1(2000,1270) ; v1(3204,2555.5) 3204,2528 3250,2482 3250,2412.66 3307.5,2355.16 3307.5,2337.34 3287,2316.84 3287,2240.46 3346.46,2181 3346.46,2136
  Layer 3 - Signal / PWR w5.25: v4(1956.03,2126.26) 1940.4,2110.63 1940.4,1907.21 1935.15,1901.96 1893.25,1901.96 1888,1896.71 1888,1886.21 1893.25,1880.96 1935.15,1880.96 1940.4,1875.71 1940.4,1865.21 1935.15,1859.96 1893.25,1859.96 1888,1854.71 1888,1844.21 1893.25,1838.96 1935.15,1838.96 1940.4,1833.71 1940.4,1824.46 1971.8,1793.06 1971.8,1634.3 1956.03,1618.53 v4(1956.03,1566.26) 1940.4,1550.63 1940.4,1445.26 1930,1434.86 1930,1370 1935,1365 1935,1334.99 v1(2000,1270)
  Layer 4 - Signal / PWR w5.25: v4(1956.03,2126.26) 1956.03,2176.62 1876.5,2256.15 1876.5,2405.1 1965.1,2493.7 2309.4,2493.7 2314.65,2498.95 2314.65,2536.25 2319.9,2541.5 2330.4,2541.5 2335.65,2536.25 2335.65,2498.95 2340.9,2493.7 2351.4,2493.7 2356.65,2498.95 2356.65,2536.25 2361.9,2541.5 2372.4,2541.5 2377.65,2536.25 2377.65,2498.95 2382.9,2493.7 2393.4,2493.7 2398.65,2498.95 2398.65,2536.25 2403.9,2541.5 2414.4,2541.5 2419.65,2536.25 2419.65,2498.95 2424.9,2493.7 2435.4,2493.7 2440.65,2498.95 2440.65,2536.25 2445.9,2541.5 2456.4,2541.5 2461.65,2536.25 2461.65,2498.95 2466.9,2493.7 2477.4,2493.7 2482.65,2498.95 2482.65,2536.25 2487.9,2541.5 2498.4,2541.5 2503.65,2536.25 2503.65,2498.95 2508.9,2493.7 2520.8,2493.7 2565.97,2538.87 3187.37,2538.87 v1(3204,2555.5)
H_DDR1_A2: R71.1 U13.AD19 U14.P3 U15.P3 | length 4341
  Layer 1 - Top Layer w4: v4(1956.03,1723.73) U15.P3@1971.77,1707.99 ; v4(1956.03,2283.73) U14.P3@1971.77,2267.99 ; U13.AD19@3346.46,2081.5 3359.15,2094.19 3359.15,2136
  Layer 1 - Top Layer w5: R71.1@1860,1239.68 v1(1860,1270) ; v1(3239,2546) 3239,2509 3261,2487 3261,2415.81 3317.5,2359.31 3317.5,2333.18 3299,2314.68 3299,2242.62 3359.15,2182.47 3359.15,2136
  Layer 3 - Signal / PWR w5.25: v1(1860,1270) 1825,1304.99 1825,1524 1956.03,1655.03 v4(1956.03,1723.73)
  Layer 6 - Bottom Layer w5: v4(1956.03,1723.73) 1940.53,1739.23 1917.76,1739.23 1908.54,1748.45 1908.54,1761.65 1908.53,1798.48 1895,1812.01 1895,1974 1972.03,2051.03 1972.03,2119.97 1971.53,2120.47 1971.53,2151.47 1961,2162 1926,2162 1912,2176 1912,2213 1917,2218 1991,2218 1996,2223 1996,2233 1991,2238 1917,2238 1912,2243 1912,2253 1921,2262 1950,2262 1956.03,2268.03 v4(1956.03,2283.73) 1940.53,2299.23 1940.53,2563.73 1956.8,2580 1972.08,2580 1977.08,2575 1977.08,2510.8 1982.08,2505.8 1990.8,2505.8 1997.08,2512.08 1997.08,2575 2002.08,2580 2012.08,2580 2017.08,2575 2017.08,2514.1 2023.48,2507.7 2030.68,2507.7 2037.08,2514.1 2037.08,2575 2042.08,2580 2056.98,2580 2061.98,2575 2061.98,2543.9 2066.98,2538.9 2076.98,2538.9 2081.98,2543.9 2081.98,2575 2086.98,2580 2096.98,2580 2101.98,2575 2101.98,2543.9 2106.98,2538.9 2116.98,2538.9 2121.98,2543.9 2121.98,2575 2126.98,2580 2136.98,2580 2141.98,2575 2141.98,2543.9 2146.98,2538.9 2156.98,2538.9 2161.98,2543.9 2161.98,2575 2166.98,2580 2176.98,2580 2181.98,2575 2181.98,2543.9 2186.98,2538.9 2196.98,2538.9 2201.98,2543.9 2201.98,2575 2206.98,2580 2216.98,2580 2221.98,2575 2221.98,2543.9 2226.98,2538.9 2236.98,2538.9 2241.98,2543.9 2241.98,2575 2246.98,2580 2256.98,2580 2261.98,2575 2261.98,2543.9 2266.98,2538.9 2276.98,2538.9 2281.98,2543.9 2281.98,2575 2286.98,2580 2296.98,2580 2301.98,2575 2301.98,2543.9 2306.98,2538.9 3117.3,2538.9 3150.4,2572 3213,2572 v1(3239,2546)
H_DDR1_A3: R72.1 U13.AB19 U14.N2 U15.N2 | length 4124.2
  Layer 1 - Top Layer w4: v4(1987.53,1755.22) U15.N2@2003.27,1739.49 ; v4(1987.53,2315.22) U14.N2@2003.27,2299.49 ; v3(3333.8,2040) U13.AB19@3346.46,2030.32
  Layer 1 - Top Layer w5: R72.1@2175,1239.68 v1(2175,1270)
  Layer 3 - Signal / PWR w5.25: v1(2175,1270) 2050,1394.99 2050,1435 2003.2,1481.8 2003.2,1739.3 1987.53,1754.97 v4(1987.53,1755.22) 2003.2,1770.89 2003.2,1921.79 1971.9,1953.09 1971.9,2141.9 2002,2172 2095,2172 2107,2184 2107,2215.99 2088.99,2234 2038.01,2234 2003.39,2268.62 2003.39,2299.36 v4(1987.53,2315.22) 2003.2,2330.89 2003.2,2457.1 2010.8,2464.7 2010.8,2504.4 2030,2523.6 2675.6,2523.6 2705.4,2553.4 2893.1,2553.4 2898.35,2548.15 2898.35,2528.85 2903.6,2523.6 2914.1,2523.6 2919.35,2528.85 2919.35,2548.15 2924.6,2553.4 2935.1,2553.4 2940.35,2548.15 2940.35,2528.85 2945.6,2523.6 2956.1,2523.6 2961.35,2528.85 2961.35,2548.15 2966.6,2553.4 2977.1,2553.4 2982.35,2548.15 2982.35,2528.85 2987.6,2523.6 2998.1,2523.6 3003.35,2528.85 3003.35,2548.15 3008.6,2553.4 3019.1,2553.4 3024.35,2548.15 3024.35,2528.85 3029.6,2523.6 3040.1,2523.6 3045.35,2528.85 3045.35,2548.15 3050.6,2553.4 3061.1,2553.4 3066.35,2548.15 3066.35,2528.85 3071.6,2523.6 3092.3,2523.6 3170,2445.9 3257.8,2445.9 3272.7,2431 3401,2431 3440,2392 3440,2263.65 3416.35,2240 3363.66,2240 3341.63,2217.97 3341.63,2091 3336.63,2086 3325,2086 3320,2091 3320,2231.75 3314.75,2237 3304.25,2237 3299,2231.75 3299,2073 3303,2069 3328.54,2069 3333.8,2063.74 v3(3333.8,2040)
H_DDR1_A4: R74.1 U13.AD20 U14.P8 U15.P8 | length 3814.8
  Layer 1 - Top Layer w4: v4(1956.03,1534.77) U15.P8@1971.77,1550.51 ; 3308.1,2136 3308.1,2094.27 U13.AD20@3320.87,2081.5
  Layer 1 - Top Layer w5: v4(1956.03,2094.77) U14.P8@1971.77,2110.51 ; R74.1@2070,1239.68 v1(2070,1270) ; v1(3169.1,2555.5) 3182,2542.6 3182,2531 3214,2499 3214,2420.34 3257,2377.34 3257,2228 3308.1,2176.9 3308.1,2136
  Layer 4 - Signal / PWR w5.25: v1(2070,1270) 1980,1360 1980,1400 1940.3,1439.7 1940.3,1519.04 v4(1956.03,1534.77) 1940.17,1550.63 1940.17,1572.73 1931.01,1581.89 1869.11,1581.89 1861,1590 1861,1915.05 1855.75,1920.3 1844.25,1920.3 1839,1925.55 1839,1936.05 1844.25,1941.3 1855.75,1941.3 1861,1946.55 1861,1987.25 1855.75,1992.5 1842.25,1992.5 1837,1997.75 1837,2008.25 1842.25,2013.5 1855.75,2013.5 1861,2018.75 1861,2029 1879.64,2047.64 1886.55,2047.64 1899.5,2047.63 1931.01,2047.64 1940.17,2056.8 1940.17,2078.91 v4(1956.03,2094.77) 1940.3,2110.5 1940.3,2166.18 1864.8,2241.68 1864.8,2411.71 1973.39,2520.3 2008.3,2520.3 2013.55,2525.55 2013.55,2553.45 2018.8,2558.7 2029.3,2558.7 2034.55,2553.45 2034.55,2525.55 2039.8,2520.3 2050.3,2520.3 2055.55,2525.55 2055.55,2553.45 2060.8,2558.7 2071.3,2558.7 2076.55,2553.45 2076.55,2525.55 2081.8,2520.3 2092.3,2520.3 2097.55,2525.55 2097.55,2553.45 2102.8,2558.7 2113.3,2558.7 2118.55,2553.45 2118.55,2525.55 2123.8,2520.3 2134.3,2520.3 2139.55,2525.55 2139.55,2553.45 2144.8,2558.7 2155.3,2558.7 2160.55,2553.45 2160.55,2525.55 2165.8,2520.3 2176.3,2520.3 2181.55,2525.55 2181.55,2553.45 2186.8,2558.7 2197.3,2558.7 2202.55,2553.45 2202.55,2525.55 2207.8,2520.3 2218.3,2520.3 2223.55,2525.55 2223.55,2553.45 2228.8,2558.7 2239.3,2558.7 2244.55,2553.45 2244.55,2525.55 2249.8,2520.3 2269.15,2520.3 2304.35,2555.5 v1(3169.1,2555.5)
